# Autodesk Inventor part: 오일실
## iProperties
IsCustomPart: 0
Created: 2009-02
Part Number: 오일실
Material: 고무
Description: 오일-실
Document SubType Name: Modeling
Standard: KS B 2804
Designer: SeoGD™ [www.esajin.kr]
Standards Organization: KS
Language: ko-KR
Size Designation: D - 17 32 8
Categories: <MemberInstance><Categories><Category DisplayName="샤프트 부품" InternalName="7f7aeb1f-a693-4053-b835-cee3144e0d98" Mnemonic="SHFT"><Category DisplayName="실링" Intern
Density: 0.93 g/cm^3
Author: SeoGD™ [www.esajin.kr]
